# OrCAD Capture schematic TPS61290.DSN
size B
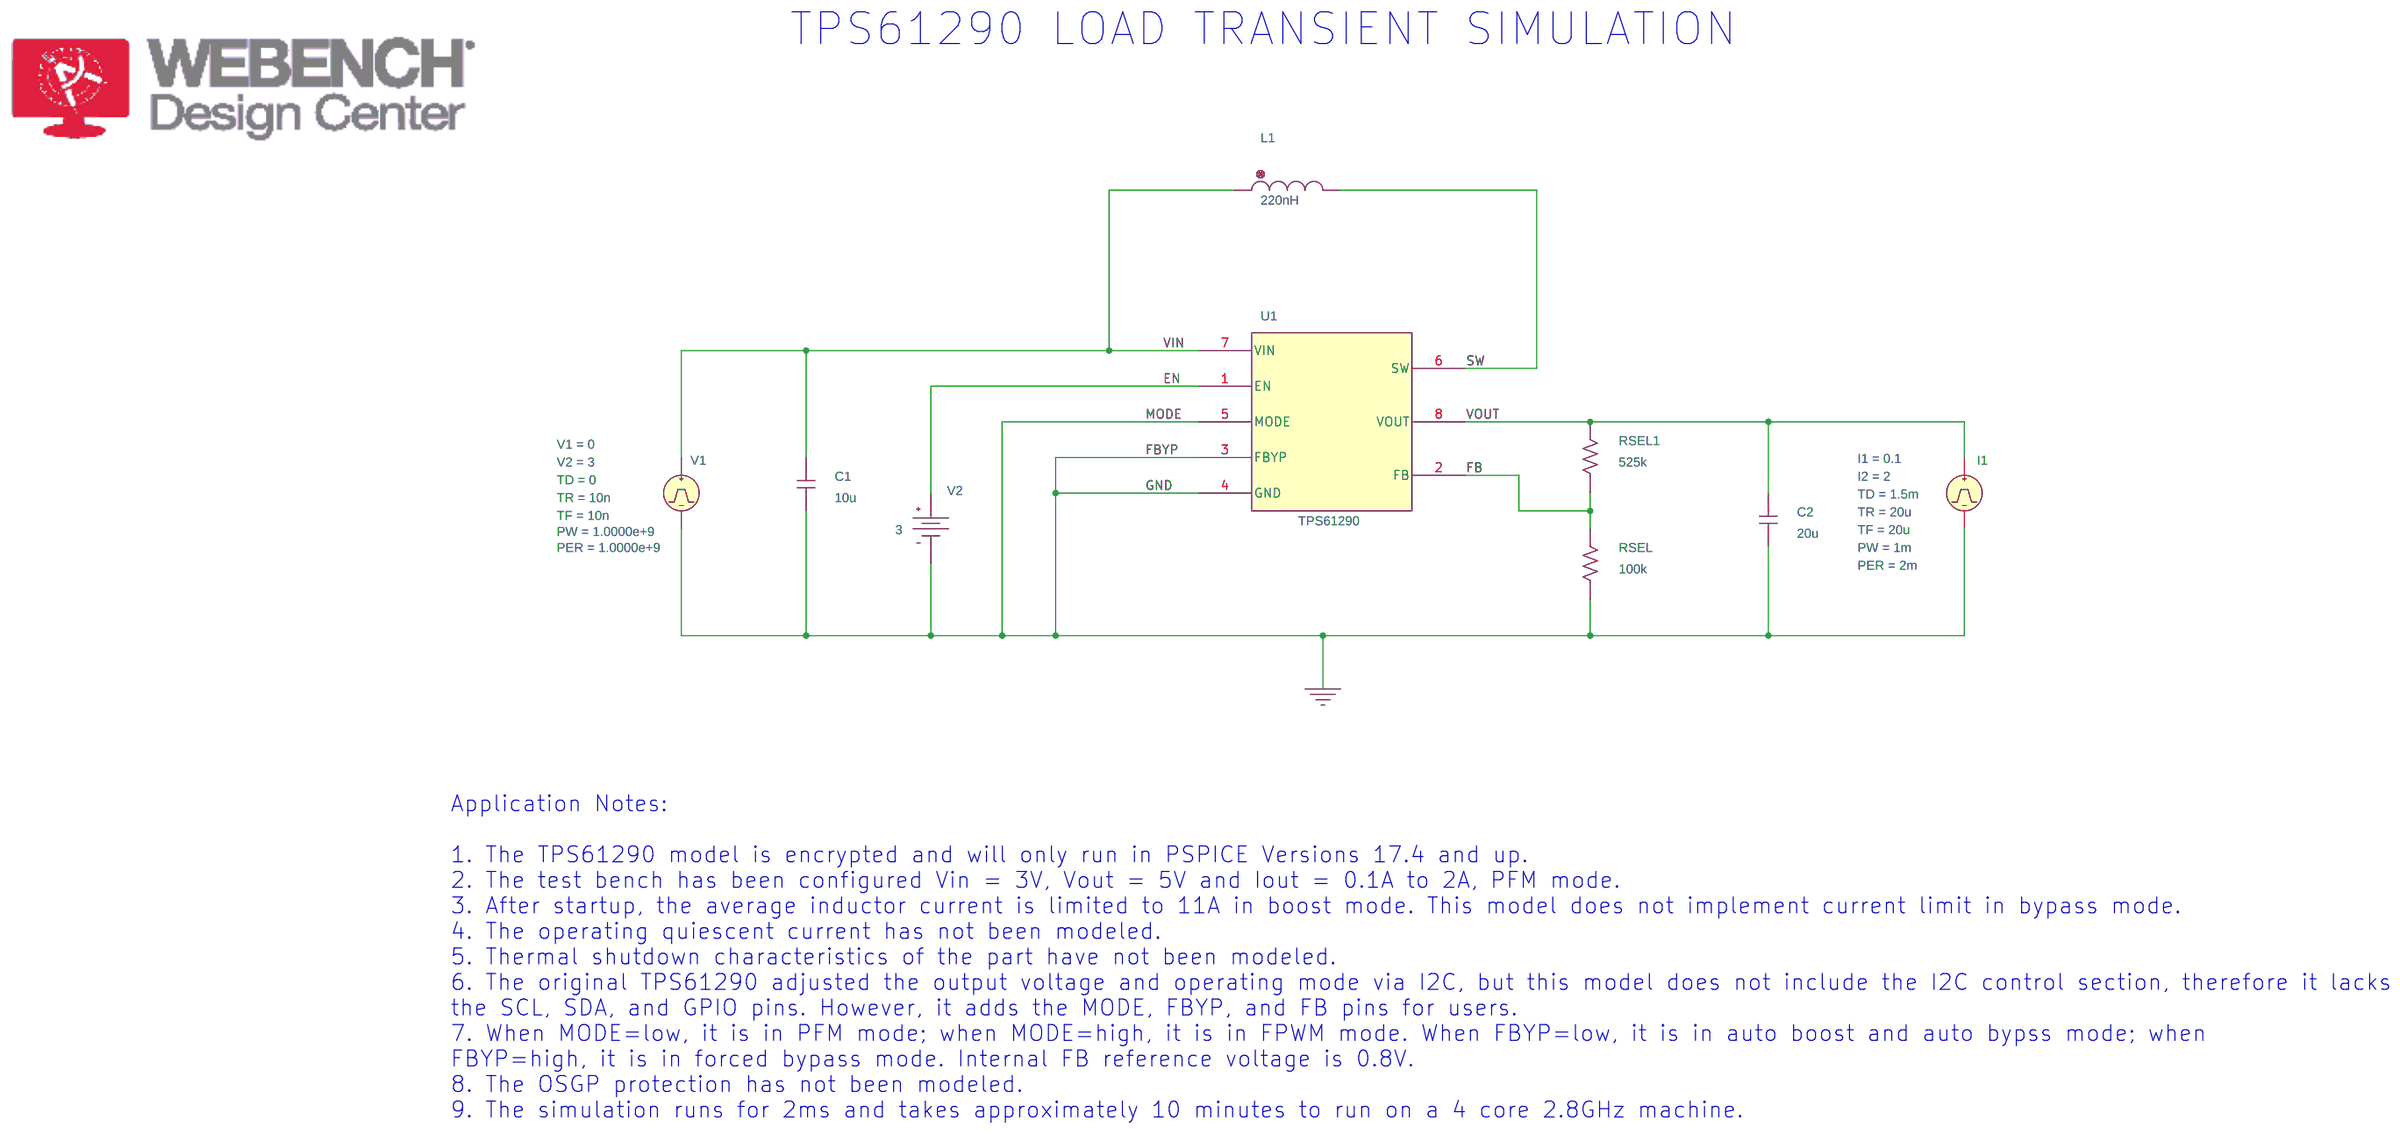
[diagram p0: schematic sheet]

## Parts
C1  10u  [RAD/CK05]
C2  20u  [RAD/CK05]
I1  IPULSE
L1  220nH  [DISC350x175LS200x100034]
RSEL  100k  [AX/RC05]
RSEL1  525k  [AX/RC05]
U1  TPS61290
V1  VPULSE
V2  VDC

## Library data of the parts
C1 C2 = C
I1 = IPULSE: I1: 0.1; I2: 2; PER: 2m; PW: 1m; TD: 1.5m; TF: 20u; TR: 20u
L1 = L
RSEL RSEL1 = R
U1 = TPS61290
V1 = VPULSE: AC: 0; AppProp: Pulse$Voltage$0$-1; DC: 0; PER: 1.0000e+9; PW: 1.0000e+9; TD: 0; TF: 10n; TR: 10n; V1: 0; V2: 3
V2 = VDC: DC: 3

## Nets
VIN: C1.1 L1.1 U1.7(VIN) V1.1(+)
0: C1.2 C2.2 I1.2(-) RSEL.1 U1.3(FBYP) U1.4(GND) U1.5(MODE) V1.2(-) V2.1(-)
EN: U1.1(EN) V2.0(+)
FB: RSEL.2 RSEL1.1 U1.2(FB)
SW: L1.2 U1.6(SW)
VOUT: C2.1 I1.1(+) RSEL1.2 U1.8(VOUT)

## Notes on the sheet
- TPS61290 LOAD TRANSIENT SIMULATION
- Application Notes:
  1. The TPS61290 model is encrypted and will only run in PSPICE Versions 17.4 and up.
  2. The test bench has been configured Vin = 3V, Vout = 5V and Iout = 0.1A to 2A, PFM mode.
  3. After startup, the average inductor current is limited to 11A in boost mode. This model does not implement current limit in bypass mode.
  4. The operating quiescent current has not been modeled.
  5. Thermal shutdown characteristics of the part have not been modeled.
  6. The original TPS61290 adjusted the output voltage and operating mode via I2C, but this model does not include the I2C control section, therefore it lacks
  the SCL, SDA, and GPIO pins. However, it adds the MODE, FBYP, and FB pins for users.
  7. When MODE=low, it is in PFM mode; when MODE=high, it is in FPWM mode. When FBYP=low, it is in auto boost and auto bypss mode; when
  FBYP=high, it is in forced bypass mode. Internal FB reference voltage is 0.8V.
  8. The OSGP protection has not been modeled.
  9. The simulation runs for 2ms and takes approximately 10 minutes to run on a 4 core 2.8GHz machine.
